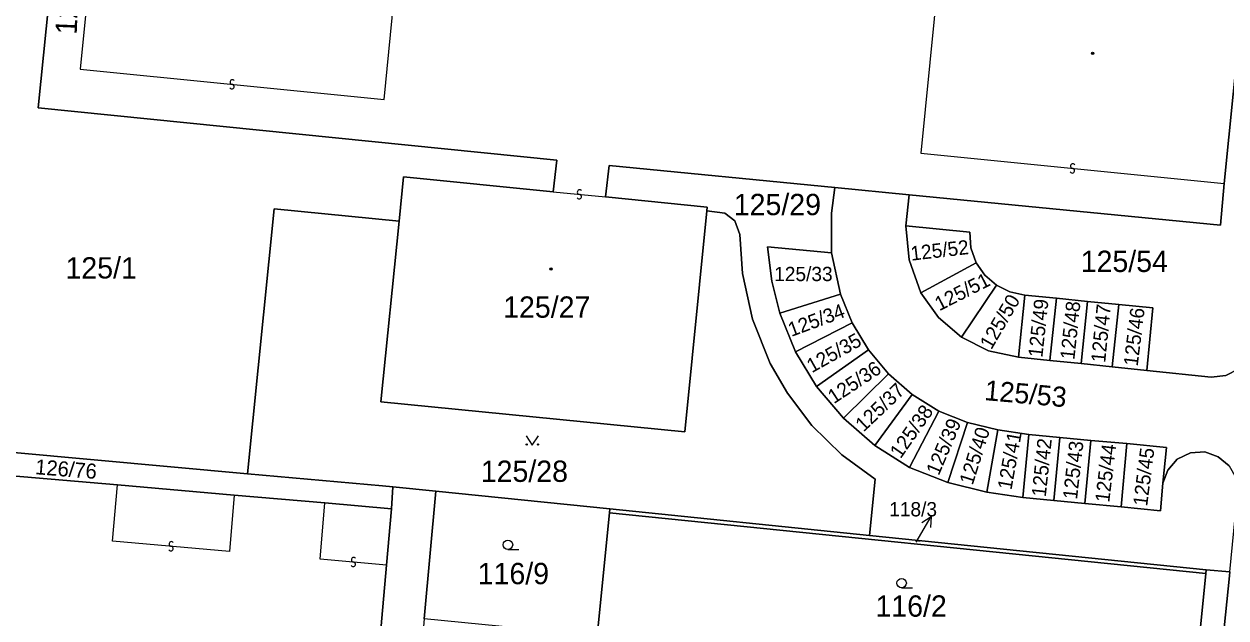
# Model space of a CAD drawing. Extents: x -598233 to -596890, y -1157848 to -1156431.
# Drawn here: x -597943.3 to -597847.5, y -1156929.2 to -1156881.8 of the extents above; entities that cross this region are included whole.
import ezdxf

# ---------------------------------------------------------------- set-up
doc = ezdxf.new("R2010")
doc.units = 0
for name, color, linetype in [('Level 1', 7, 'Continuous'), ('Level 13', 7, 'Continuous'), ('Level 3', 7, 'Continuous'), ('Level 4', 7, 'Continuous'), ('Level 5', 7, 'Continuous'), ('Level 57', 7, 'Continuous'), ('Level 60', 7, 'Continuous')]:
    doc.layers.add(name, color=color, linetype=linetype)

msp = doc.modelspace()

# ---------------------------------------------------------------- linework, layer by layer
at = {"layer": 'Level 1'}
for points in [[(-597901.17, -1156895.17), (-597900.87, -1156892.64), (-597942.21, -1156888.49), (-597940.73, -1156873.76)], [(-597847.67, -1156894.51), (-597845.88, -1156876.55), (-597853.45, -1156875.79)], [(-597878.73, -1156894.84), (-597896.71, -1156893.08), (-597896.99, -1156895.59)], [(-597913.45, -1156897.52), (-597913.09, -1156893.99), (-597901.17, -1156895.17)], [(-597878.98, -1156900.05), (-597878.98, -1156896.88), (-597878.73, -1156894.84)], [(-597872.79, -1156895.42), (-597878.73, -1156894.84)], [(-597847.67, -1156894.51), (-597847.98, -1156897.84), (-597872.79, -1156895.42)], [(-597896.99, -1156895.59), (-597888.88, -1156896.39), (-597888.91, -1156896.69)], [(-597872.79, -1156895.42), (-597873.05, -1156897.88)], [(-597925.52, -1156917.66), (-597923.4, -1156896.53), (-597913.45, -1156897.52)], [(-597888.91, -1156896.69), (-597890.67, -1156914.32), (-597914.9, -1156911.93), (-597913.45, -1156897.52)], [(-597888.91, -1156896.69), (-597887.48, -1156896.87), (-597886.68, -1156897.48), (-597886.3, -1156898.57), (-597886.08, -1156901.68), (-597885.27, -1156905.32), (-597883.86, -1156908.88), (-597882.5, -1156911.24), (-597880.56, -1156913.8), (-597878.16, -1156916.15), (-597875.51, -1156918.1), (-597875.95, -1156922.58)], [(-597871.87, -1156903.22), (-597872.79, -1156900.6), (-597873.05, -1156897.88)], [(-597873.05, -1156897.88), (-597867.96, -1156898.4), (-597867.88, -1156899.65), (-597867.46, -1156900.85)], [(-597883.09, -1156904.86), (-597883.73, -1156902.3), (-597884.08, -1156899.56), (-597878.98, -1156900.05)], [(-597878.98, -1156900.05), (-597878.27, -1156903.33)], [(-597867.46, -1156900.85), (-597871.87, -1156903.22)], [(-597867.46, -1156900.85), (-597866.75, -1156901.83), (-597865.84, -1156902.62)], [(-597868.63, -1156906.78), (-597865.84, -1156902.62)], [(-597865.84, -1156902.62), (-597864.77, -1156903.14), (-597863.57, -1156903.43)], [(-597883.09, -1156904.86), (-597878.27, -1156903.33)], [(-597878.27, -1156903.33), (-597877.34, -1156905.62)], [(-597871.87, -1156903.22), (-597870.45, -1156905.19), (-597868.63, -1156906.78)], [(-597863.57, -1156903.43), (-597864.07, -1156908.36)], [(-597863.57, -1156903.43), (-597861.06, -1156903.67)], [(-597861.59, -1156908.63), (-597861.06, -1156903.67)], [(-597861.06, -1156903.67), (-597858.57, -1156903.92)], [(-597858.57, -1156903.92), (-597859.08, -1156908.88)], [(-597858.57, -1156903.92), (-597856.09, -1156904.17)], [(-597856.6, -1156909.14), (-597856.09, -1156904.17)], [(-597856.09, -1156904.17), (-597853.36, -1156904.42), (-597853.85, -1156909.43)], [(-597881.84, -1156907.93), (-597883.09, -1156904.86)], [(-597881.84, -1156907.93), (-597877.34, -1156905.62)], [(-597877.34, -1156905.62), (-597876.04, -1156907.79)], [(-597864.07, -1156908.36), (-597866.47, -1156907.85), (-597868.63, -1156906.78)], [(-597853.85, -1156909.43), (-597848.73, -1156909.95), (-597847.54, -1156909.83), (-597846.51, -1156909.29), (-597845.79, -1156908.37), (-597845.43, -1156907.28)], [(-597880.17, -1156910.71), (-597881.84, -1156907.93)], [(-597880.17, -1156910.71), (-597876.04, -1156907.79)], [(-597876.04, -1156907.79), (-597874.44, -1156909.69)], [(-597864.07, -1156908.36), (-597861.59, -1156908.63)], [(-597859.08, -1156908.88), (-597861.59, -1156908.63)], [(-597859.08, -1156908.88), (-597856.6, -1156909.14)], [(-597853.85, -1156909.43), (-597856.6, -1156909.14)], [(-597878.02, -1156913.24), (-597874.44, -1156909.69)], [(-597874.44, -1156909.69), (-597872.55, -1156911.33)], [(-597878.02, -1156913.24), (-597880.17, -1156910.71)], [(-597875.54, -1156915.4), (-597872.55, -1156911.33)], [(-597872.55, -1156911.33), (-597870.42, -1156912.66)], [(-597875.54, -1156915.4), (-597878.02, -1156913.24)], [(-597872.77, -1156917.15), (-597870.42, -1156912.66)], [(-597870.42, -1156912.66), (-597868.15, -1156913.57)], [(-597869.71, -1156918.37), (-597868.15, -1156913.57)], [(-597868.15, -1156913.57), (-597865.73, -1156914.16)], [(-597866.61, -1156919.14), (-597865.73, -1156914.16)], [(-597865.73, -1156914.16), (-597863.26, -1156914.52)], [(-597863.26, -1156914.52), (-597863.74, -1156919.55)], [(-597860.79, -1156914.76), (-597863.26, -1156914.52)], [(-597861.27, -1156919.79), (-597860.79, -1156914.76)], [(-597860.79, -1156914.76), (-597858.31, -1156915)], [(-597858.31, -1156915), (-597858.79, -1156920.02)], [(-597855.43, -1156915.26), (-597858.31, -1156915)], [(-597950.3, -1156915.42), (-597925.52, -1156917.66)], [(-597872.77, -1156917.15), (-597875.54, -1156915.4)], [(-597855.43, -1156915.26), (-597855.89, -1156920.29)], [(-597852.56, -1156918.42), (-597852.28, -1156915.56), (-597855.43, -1156915.26)], [(-597852.56, -1156918.42), (-597852.18, -1156917.37), (-597851.42, -1156916.5), (-597850.37, -1156916), (-597849.22, -1156915.92), (-597848.15, -1156916.3), (-597847.28, -1156917.04), (-597846.72, -1156918.02), (-597846.62, -1156919.2)], [(-597946.81, -1156917.61), (-597935.89, -1156918.55)], [(-597913.96, -1156918.71), (-597914.77, -1156918.63), (-597925.52, -1156917.66)], [(-597869.71, -1156918.37), (-597872.77, -1156917.15)], [(-597935.89, -1156918.55), (-597926.59, -1156919.36)], [(-597914.06, -1156920.46), (-597913.96, -1156918.71)], [(-597913.96, -1156918.71), (-597910.53, -1156919.06)], [(-597866.61, -1156919.14), (-597869.71, -1156918.37)], [(-597855.89, -1156920.29), (-597852.76, -1156920.61), (-597852.56, -1156918.42)], [(-597926.59, -1156919.36), (-597919.36, -1156919.99)], [(-597910.53, -1156919.06), (-597911.45, -1156929.24)], [(-597910.53, -1156919.06), (-597896.66, -1156920.47)], [(-597863.74, -1156919.55), (-597866.61, -1156919.14)], [(-597863.74, -1156919.55), (-597861.27, -1156919.79)], [(-597858.79, -1156920.02), (-597861.27, -1156919.79)], [(-597919.36, -1156919.99), (-597914.06, -1156920.46)], [(-597914.06, -1156920.46), (-597914.45, -1156924.94)], [(-597896.69, -1156920.78), (-597897.67, -1156930.59)], [(-597896.66, -1156920.47), (-597896.69, -1156920.78)], [(-597849.14, -1156925.62), (-597896.69, -1156920.78)], [(-597875.95, -1156922.58), (-597896.66, -1156920.47)], [(-597858.79, -1156920.02), (-597855.89, -1156920.29)], [(-597875.95, -1156922.58), (-597849.11, -1156925.31)], [(-597914.45, -1156924.94), (-597915.19, -1156933.41), (-597909.62, -1156933.91), (-597910.84, -1156948.01)], [(-597847.24, -1156925.49), (-597847.27, -1156925.81), (-597848.23, -1156935.41), (-597848.26, -1156935.77), (-597848.8, -1156941.13), (-597849.94, -1156952.57), (-597850.78, -1156961.04)], [(-597850.1, -1156935.23), (-597849.14, -1156925.62)], [(-597849.11, -1156925.31), (-597849.14, -1156925.62)], [(-597847.24, -1156925.49), (-597849.11, -1156925.31)]]:
    msp.add_lwpolyline(points, dxfattribs=at)
at = {"layer": 'Level 13'}
for centre, start, end in [((-597926.74, -1156886.427), 31.66916, 263.76716), ((-597926.779, -1156886.793), 211.45471, 84.04471), ((-597859.75, -1156893.127), 31.68558, 263.78358), ((-597859.789, -1156893.493), 211.47113, 84.06113), ((-597899.06, -1156895.197), 31.635, 263.733), ((-597899.099, -1156895.563), 211.42054, 84.01054), ((-597931.638, -1156923.624), 212.35, 84.44799), ((-597931.603, -1156923.257), 32.13554, 264.72554), ((-597917.108, -1156924.884), 212.28595, 84.38394), ((-597917.073, -1156924.517), 32.07149, 264.66149)]:
    msp.add_arc(centre, 0.184, start, end, dxfattribs=at)
at = {"layer": 'Level 3'}
for points in [[(-597937.1, -1156867.44), (-597938.88, -1156885.4), (-597914.65, -1156887.82), (-597912.89, -1156869.86)], [(-597870.08, -1156874.13), (-597871.87, -1156892.1), (-597847.67, -1156894.51)], [(-597901.17, -1156895.17), (-597896.99, -1156895.59)], [(-597926.59, -1156919.36), (-597926.96, -1156923.85), (-597936.29, -1156923.03), (-597935.89, -1156918.55)], [(-597914.45, -1156924.94), (-597919.73, -1156924.47), (-597919.36, -1156919.99)]]:
    msp.add_lwpolyline(points, dxfattribs=at)
at = {"layer": 'Level 5'}
for p, q in [((-597904.77, -1156923.7), (-597903.895, -1156923.7)), ((-597873.39, -1156926.76), (-597872.515, -1156926.76))]:
    msp.add_line(p, q, dxfattribs=at)
msp.add_lwpolyline([(-597903.331, -1156914.63), (-597902.83, -1156915.38), (-597902.33, -1156914.63)], dxfattribs=at)
for centre, radius in [((-597858.17, -1156884.14), 0.09), ((-597858.17, -1156884.14), 0.0521), ((-597901.35, -1156901.33), 0.09), ((-597901.35, -1156901.33), 0.0521), ((-597903.28, -1156915.33), 0.05), ((-597902.381, -1156915.33), 0.05), ((-597904.77, -1156923.325), 0.375), ((-597873.39, -1156926.385), 0.375)]:
    msp.add_circle(centre, radius, dxfattribs=at)
at = {"layer": 'Level 57'}
msp.add_line((-597872.24, -1156923.11), (-597871.03, -1156921.06), dxfattribs=at)
msp.add_lwpolyline([(-597871.775, -1156921.542), (-597871.03, -1156921.06), (-597871.092, -1156921.945)], dxfattribs=at)
at = {"layer": 'Level 60'}
for points in [[(-597924.66, -1156868.68), (-597912.89, -1156869.86), (-597870.08, -1156874.13), (-597853.45, -1156875.79), (-597845.88, -1156876.55), (-597847.67, -1156894.51), (-597847.98, -1156897.84), (-597872.79, -1156895.42), (-597878.73, -1156894.84), (-597896.71, -1156893.08), (-597896.99, -1156895.59), (-597888.88, -1156896.39), (-597888.91, -1156896.69), (-597890.67, -1156914.32), (-597914.9, -1156911.93), (-597913.45, -1156897.52), (-597913.09, -1156893.99), (-597901.17, -1156895.17), (-597900.87, -1156892.64), (-597942.21, -1156888.49), (-597940.73, -1156873.76), (-597940.07, -1156867.14), (-597937.1, -1156867.44)], [(-597913.09, -1156893.99), (-597913.45, -1156897.52), (-597923.4, -1156896.53), (-597925.52, -1156917.66), (-597950.3, -1156915.42), (-597949.77, -1156909.6), (-597949.34, -1156904.8), (-597949.01, -1156901.17), (-597945.65, -1156891.92), (-597944.5, -1156880.94), (-597944.05, -1156880.98), (-597943.52, -1156875.67), (-597943.29, -1156873.42), (-597940.73, -1156873.76), (-597942.21, -1156888.49), (-597900.87, -1156892.64), (-597901.17, -1156895.17)], [(-597890.67, -1156914.32), (-597888.91, -1156896.69), (-597887.48, -1156896.87), (-597886.68, -1156897.48), (-597886.3, -1156898.57), (-597886.08, -1156901.68), (-597885.27, -1156905.32), (-597883.86, -1156908.88), (-597882.5, -1156911.24), (-597880.56, -1156913.8), (-597878.16, -1156916.15), (-597875.51, -1156918.1), (-597875.95, -1156922.58), (-597896.66, -1156920.47), (-597910.53, -1156919.06), (-597913.96, -1156918.71), (-597914.77, -1156918.63), (-597925.52, -1156917.66), (-597923.4, -1156896.53), (-597913.45, -1156897.52), (-597914.9, -1156911.93)], [(-597867.46, -1156900.85), (-597871.87, -1156903.22), (-597872.79, -1156900.6), (-597873.05, -1156897.88), (-597867.96, -1156898.4), (-597867.88, -1156899.65)], [(-597878.27, -1156903.33), (-597883.09, -1156904.86), (-597883.73, -1156902.3), (-597884.08, -1156899.56), (-597878.98, -1156900.05)], [(-597871.87, -1156903.22), (-597867.46, -1156900.85), (-597866.75, -1156901.83), (-597865.84, -1156902.62), (-597868.63, -1156906.78), (-597870.45, -1156905.19)], [(-597868.63, -1156906.78), (-597865.84, -1156902.62), (-597864.77, -1156903.14), (-597863.57, -1156903.43), (-597864.07, -1156908.36), (-597866.47, -1156907.85)], [(-597877.34, -1156905.62), (-597881.84, -1156907.93), (-597883.09, -1156904.86), (-597878.27, -1156903.33)], [(-597864.07, -1156908.36), (-597863.57, -1156903.43), (-597861.06, -1156903.67), (-597861.59, -1156908.63)], [(-597861.59, -1156908.63), (-597861.06, -1156903.67), (-597858.57, -1156903.92), (-597859.08, -1156908.88)], [(-597859.08, -1156908.88), (-597858.57, -1156903.92), (-597856.09, -1156904.17), (-597856.6, -1156909.14)], [(-597856.6, -1156909.14), (-597856.09, -1156904.17), (-597853.36, -1156904.42), (-597853.85, -1156909.43)], [(-597876.04, -1156907.79), (-597880.17, -1156910.71), (-597881.84, -1156907.93), (-597877.34, -1156905.62)], [(-597874.44, -1156909.69), (-597878.02, -1156913.24), (-597880.17, -1156910.71), (-597876.04, -1156907.79)], [(-597872.55, -1156911.33), (-597875.54, -1156915.4), (-597878.02, -1156913.24), (-597874.44, -1156909.69)], [(-597870.42, -1156912.66), (-597872.77, -1156917.15), (-597875.54, -1156915.4), (-597872.55, -1156911.33)], [(-597868.15, -1156913.57), (-597869.71, -1156918.37), (-597872.77, -1156917.15), (-597870.42, -1156912.66)], [(-597865.73, -1156914.16), (-597866.61, -1156919.14), (-597869.71, -1156918.37), (-597868.15, -1156913.57)], [(-597863.26, -1156914.52), (-597863.74, -1156919.55), (-597866.61, -1156919.14), (-597865.73, -1156914.16)], [(-597952.26, -1156915.17), (-597950.3, -1156915.42), (-597925.52, -1156917.66), (-597914.77, -1156918.63), (-597913.96, -1156918.71), (-597914.06, -1156920.46), (-597919.36, -1156919.99), (-597926.59, -1156919.36), (-597935.89, -1156918.55), (-597946.81, -1156917.61), (-597952.94, -1156917.11), (-597958.35, -1156916.63), (-597958.17, -1156914.67), (-597956.4, -1156914.82)], [(-597860.79, -1156914.76), (-597861.27, -1156919.79), (-597863.74, -1156919.55), (-597863.26, -1156914.52)], [(-597858.31, -1156915), (-597858.79, -1156920.02), (-597861.27, -1156919.79), (-597860.79, -1156914.76)], [(-597855.43, -1156915.26), (-597855.89, -1156920.29), (-597858.79, -1156920.02), (-597858.31, -1156915)], [(-597852.28, -1156915.56), (-597852.56, -1156918.42), (-597852.76, -1156920.61), (-597855.89, -1156920.29), (-597855.43, -1156915.26)], [(-597896.66, -1156920.47), (-597896.69, -1156920.78), (-597897.67, -1156930.59), (-597911.45, -1156929.24), (-597910.53, -1156919.06)], [(-597896.69, -1156920.78), (-597849.14, -1156925.62), (-597850.1, -1156935.23), (-597850.54, -1156935.19), (-597897.67, -1156930.59)], [(-597849.14, -1156925.62), (-597896.69, -1156920.78), (-597896.66, -1156920.47), (-597875.95, -1156922.58), (-597849.11, -1156925.31)], [(-597849.11, -1156925.31), (-597847.24, -1156925.49), (-597847.27, -1156925.81), (-597848.23, -1156935.41), (-597848.26, -1156935.77), (-597848.8, -1156941.13), (-597849.94, -1156952.57), (-597850.78, -1156961.04), (-597852.65, -1156960.83), (-597851.81, -1156952.4), (-597850.67, -1156940.96), (-597850.14, -1156935.59), (-597850.1, -1156935.23), (-597849.14, -1156925.62)]]:
    msp.add_lwpolyline(points, close=True, dxfattribs=at)
for points in [[(-597846.51, -1156909.29), (-597847.54, -1156909.83), (-597848.73, -1156909.95), (-597853.85, -1156909.43), (-597853.36, -1156904.42), (-597856.09, -1156904.17), (-597858.57, -1156903.92), (-597861.06, -1156903.67), (-597863.57, -1156903.43), (-597864.77, -1156903.14), (-597865.84, -1156902.62), (-597866.75, -1156901.83), (-597867.46, -1156900.85), (-597867.88, -1156899.65), (-597867.96, -1156898.4), (-597873.05, -1156897.88), (-597872.79, -1156895.42), (-597847.98, -1156897.84), (-597847.67, -1156894.51), (-597845.88, -1156876.55)], [(-597836.71, -1156880.5), (-597839.09, -1156904.37), (-597840.22, -1156915.7), (-597841.26, -1156926.12), (-597844.76, -1156961.19), (-597844.54, -1156963.55), (-597850.98, -1156963.05), (-597850.78, -1156961.04), (-597849.94, -1156952.57), (-597848.8, -1156941.13), (-597848.26, -1156935.77), (-597848.23, -1156935.41), (-597847.27, -1156925.81), (-597847.24, -1156925.49), (-597846.62, -1156919.2), (-597846.37, -1156916.72), (-597845.43, -1156907.28), (-597845.37, -1156906.68), (-597842.76, -1156880.46)], [(-597847.24, -1156925.49), (-597849.11, -1156925.31), (-597875.95, -1156922.58), (-597875.51, -1156918.1), (-597878.16, -1156916.15), (-597880.56, -1156913.8), (-597882.5, -1156911.24), (-597883.86, -1156908.88), (-597885.27, -1156905.32), (-597886.08, -1156901.68), (-597886.3, -1156898.57), (-597886.68, -1156897.48), (-597887.48, -1156896.87), (-597888.91, -1156896.69), (-597888.88, -1156896.39), (-597896.99, -1156895.59), (-597896.71, -1156893.08), (-597878.73, -1156894.84), (-597878.98, -1156896.88), (-597878.98, -1156900.05), (-597884.08, -1156899.56), (-597883.73, -1156902.3), (-597883.09, -1156904.86), (-597881.84, -1156907.93), (-597880.17, -1156910.71), (-597878.02, -1156913.24), (-597875.54, -1156915.4), (-597872.77, -1156917.15), (-597869.71, -1156918.37), (-597866.61, -1156919.14), (-597863.74, -1156919.55), (-597861.27, -1156919.79), (-597858.79, -1156920.02), (-597855.89, -1156920.29), (-597852.76, -1156920.61), (-597852.56, -1156918.42), (-597852.18, -1156917.37), (-597851.42, -1156916.5), (-597850.37, -1156916), (-597849.22, -1156915.92), (-597848.15, -1156916.3), (-597847.28, -1156917.04)], [(-597847.28, -1156917.04), (-597848.15, -1156916.3), (-597849.22, -1156915.92), (-597850.37, -1156916), (-597851.42, -1156916.5), (-597852.18, -1156917.37), (-597852.56, -1156918.42), (-597852.28, -1156915.56), (-597855.43, -1156915.26), (-597858.31, -1156915), (-597860.79, -1156914.76), (-597863.26, -1156914.52), (-597865.73, -1156914.16), (-597868.15, -1156913.57), (-597870.42, -1156912.66), (-597872.55, -1156911.33), (-597874.44, -1156909.69), (-597876.04, -1156907.79), (-597877.34, -1156905.62), (-597878.27, -1156903.33), (-597878.98, -1156900.05), (-597878.98, -1156896.88), (-597878.73, -1156894.84), (-597872.79, -1156895.42), (-597873.05, -1156897.88), (-597872.79, -1156900.6), (-597871.87, -1156903.22), (-597870.45, -1156905.19), (-597868.63, -1156906.78), (-597866.47, -1156907.85), (-597864.07, -1156908.36), (-597861.59, -1156908.63), (-597859.08, -1156908.88), (-597856.6, -1156909.14), (-597853.85, -1156909.43), (-597848.73, -1156909.95), (-597847.54, -1156909.83), (-597846.51, -1156909.29)], [(-597946.81, -1156917.61), (-597935.89, -1156918.55), (-597926.59, -1156919.36), (-597919.36, -1156919.99), (-597914.06, -1156920.46), (-597914.45, -1156924.94), (-597915.19, -1156933.41), (-597909.62, -1156933.91), (-597910.84, -1156948.01), (-597911.46, -1156947.96), (-597921.95, -1156947.04), (-597922.69, -1156946.97), (-597929.92, -1156946.34), (-597930.65, -1156946.28), (-597940.08, -1156945.45), (-597940.82, -1156945.39), (-597947.85, -1156944.77)], [(-597958.75, -1156950.75), (-597911.46, -1156955.02), (-597910.97, -1156949.46), (-597910.84, -1156948.01), (-597909.62, -1156933.91), (-597915.19, -1156933.41), (-597914.45, -1156924.94), (-597914.06, -1156920.46), (-597913.96, -1156918.71), (-597910.53, -1156919.06), (-597911.45, -1156929.24), (-597911.56, -1156930.46), (-597905.98, -1156930.97), (-597906.44, -1156936.01), (-597907.47, -1156947.45), (-597908.48, -1156958.59), (-597917.25, -1156957.91), (-597961.49, -1156954.47)]]:
    msp.add_lwpolyline(points, dxfattribs=at)

# ---------------------------------------------------------------- texts
at = {"layer": 'Level 4'}
for s, height, p in [('125/29', 1.7, (-597886.772, -1156897.04)), ('125/54', 1.7, (-597859.118, -1156901.57)), ('125/1', 1.7, (-597940.041, -1156902.09)), ('125/33', 1.14, (-597883.554, -1156902.3)), ('125/27', 1.7, (-597905.156, -1156905.22)), ('125/28', 1.7, (-597906.939, -1156918.31)), ('118/3', 0.1, (-597872.24, -1156923.11)), ('116/9', 1.7, (-597907.185, -1156926.47)), ('116/2', 1.7, (-597875.48, -1156929.06))]:
    msp.add_text(s, height=height, dxfattribs=at).set_placement(p)
for s, height, rotation, p in [('125/52', 1.14, 6.6348, (-597872.616, -1156900.673)), ('125/51', 1.14, 26.92458, (-597870.385, -1156904.707)), ('125/50', 1.14, 59.83515, (-597866.243, -1156907.828)), ('125/34', 1.14, 20.30409, (-597882.187, -1156906.753)), ('125/49', 1.14, 83.84697, (-597862.176, -1156908.428)), ('125/48', 1.14, 83.92959, (-597859.624, -1156908.6)), ('125/47', 1.14, 84.22767, (-597857.168, -1156908.836)), ('125/46', 1.14, 83.02131, (-597854.578, -1156909.124)), ('125/35', 1.14, 29.25729, (-597880.548, -1156909.648)), ('125/36', 1.14, 33.47451, (-597878.794, -1156912.122)), ('125/53', 1.6, 354.93462, (-597866.832, -1156911.783)), ('125/37', 1.14, 43.57782, (-597876.42, -1156914.368)), ('125/38', 1.14, 55.18485, (-597873.474, -1156916.513)), ('125/39', 1.14, 66.95586, (-597870.437, -1156917.865)), ('125/40', 1.14, 72.51768, (-597867.733, -1156918.62)), ('125/41', 1.14, 79.78131, (-597864.64, -1156919.003)), ('125/42', 1.14, 83.99304, (-597861.904, -1156919.542)), ('125/43', 1.14, 83.5434, (-597859.413, -1156919.747)), ('125/44', 1.14, 83.06802, (-597856.847, -1156919.994)), ('125/45', 1.14, 82.74933, (-597853.823, -1156920.29)), ('126/76', 1.2, 355.5, (-597942.487, -1156917.694))]:
    msp.add_text(s, height=height, rotation=rotation, dxfattribs=at).set_placement(p)
at = {"layer": 'Level 57'}
msp.add_text('126/5', height=1.7, rotation=87.54849, dxfattribs=at).set_placement((-597939.151, -1156882.666))
msp.add_text('118/3', height=1.14, dxfattribs=at).set_placement((-597874.384, -1156921.06))

doc.saveas('drawing.dxf')
